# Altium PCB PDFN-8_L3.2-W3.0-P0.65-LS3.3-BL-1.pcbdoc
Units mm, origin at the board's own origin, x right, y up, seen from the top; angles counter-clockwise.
Board outline 15.91 x 17.12 mm, 2 copper layers (Top Layer, Bottom Layer), stack 0 mm thick; 1 components, 0 nets, 9 pads, 0 vias.
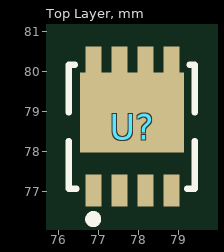
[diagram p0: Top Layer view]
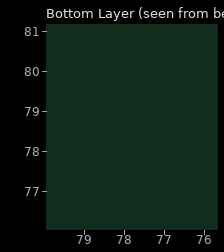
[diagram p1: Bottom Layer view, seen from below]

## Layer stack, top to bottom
Top Layer: signal copper (thickness not stored)
Bottom Layer: signal copper (thickness not stored)

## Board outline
85.76,69.85 69.85,69.85 69.85,86.97 85.76,86.97

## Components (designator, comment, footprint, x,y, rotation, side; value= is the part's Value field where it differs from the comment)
U? "" PDFN-8_L3.2-W3.0-P0.65-LS3.3-BL-1 77.835,78.61 r0 top

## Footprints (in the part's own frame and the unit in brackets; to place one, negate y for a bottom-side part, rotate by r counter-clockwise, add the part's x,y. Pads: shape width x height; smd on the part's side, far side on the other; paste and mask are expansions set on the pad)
PDFN-8_L3.2-W3.0-P0.65-LS3.3-BL-1 [mm]
  rect 0.4x0.8 smd paste-100 mask+0.051: 1(-0.975,-1.6) 2(-0.325,-1.6) 3(0.325,-1.6) 4(0.975,-1.6) 5(0.975,1.6) 6(0.325,1.6) 7(-0.325,1.6) 8(-0.975,1.6)
  rect 2.6x2 smd paste-100 mask+0.051: 9(-0.005,0.35)
  silkscreen extent -1.59,-2.41 1.56,1.55

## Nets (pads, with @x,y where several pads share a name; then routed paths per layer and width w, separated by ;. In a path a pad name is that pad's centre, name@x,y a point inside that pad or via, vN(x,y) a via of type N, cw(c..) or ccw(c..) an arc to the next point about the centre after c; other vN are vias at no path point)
pads on no net: U?.1 U?.2 U?.3 U?.4 U?.5 U?.6 U?.7 U?.8 U?.9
